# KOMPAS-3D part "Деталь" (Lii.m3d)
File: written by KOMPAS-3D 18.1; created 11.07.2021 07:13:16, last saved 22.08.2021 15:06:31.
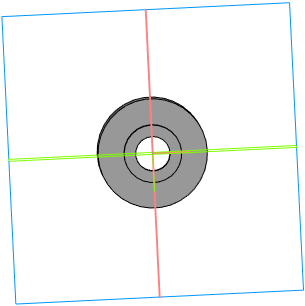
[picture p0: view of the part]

Document properties: Автор: 111; Полное имя файла: C:\Users\admin\Desktop\ffb\Lii.m3d

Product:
- Part/product: Деталь
    Масса: 0.0864121
    source file: ..\4.cdw

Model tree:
1. Эскиз:1
2. Элемент выдавливания:1
     Расстояние 1 = 45
3. Эскиз:4
4. Элемент выдавливания:3
     Расстояние 1 = 10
